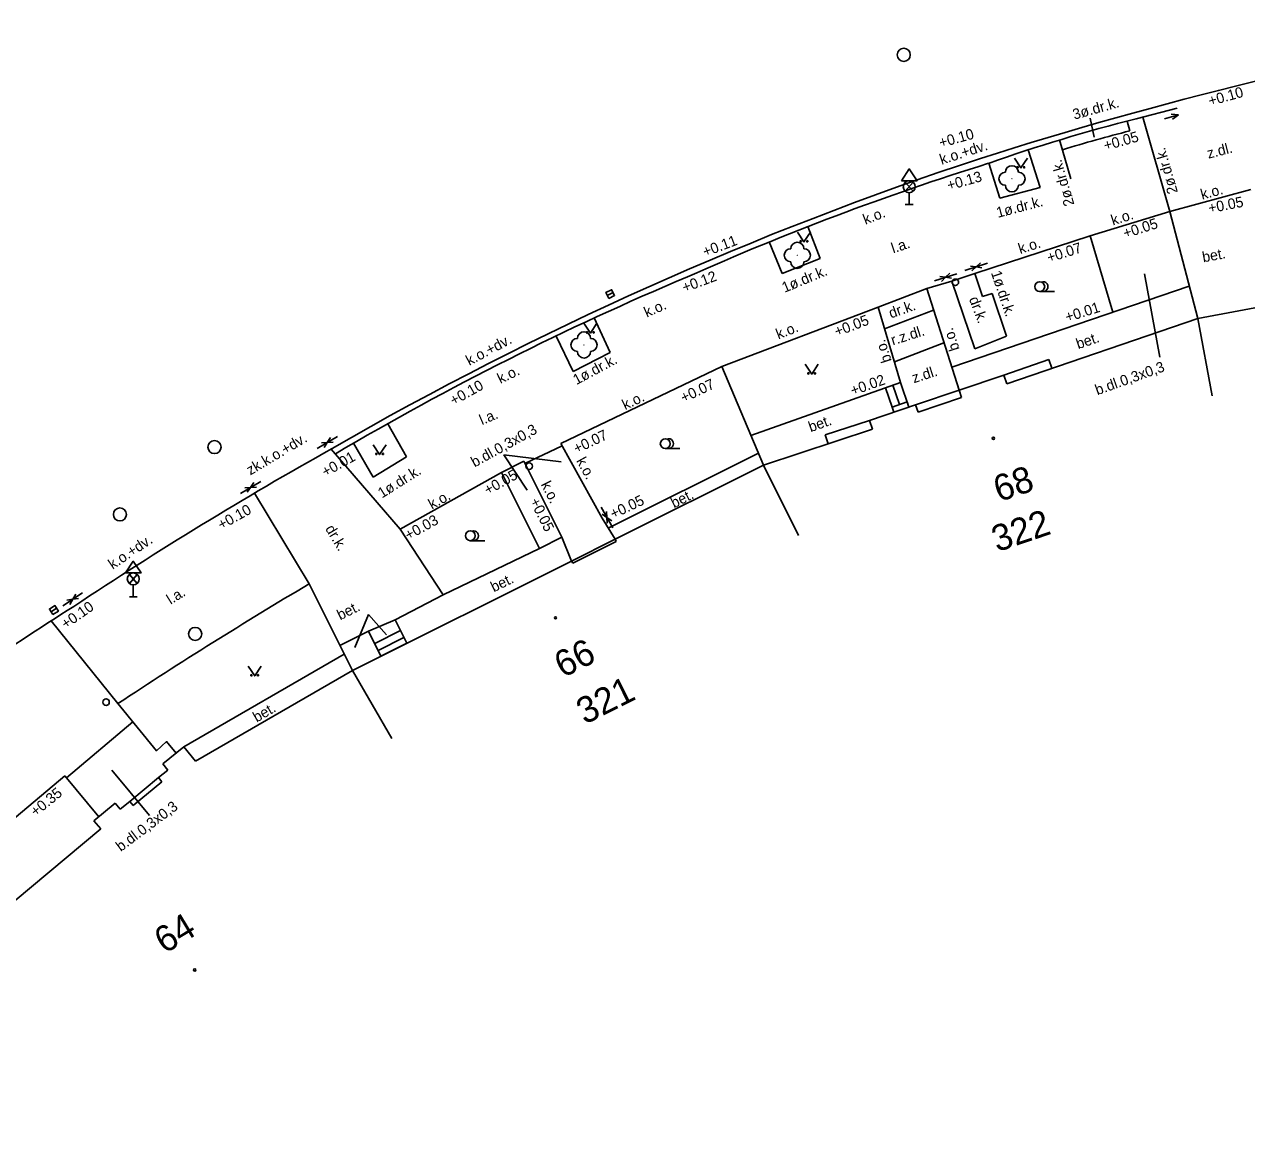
# Model space of a CAD drawing. Extents: x -597862 to -597276, y -1159156 to -1158889.
# Drawn here: x -597817.21 to -597770.58, y -1159122.27 to -1159079.98 of the extents above; entities that cross this region are included whole.
import ezdxf

# ---------------------------------------------------------------- set-up
doc = ezdxf.new("R2010")
doc.units = 0
for name, color, linetype in [('Vrstva 12', 7, 'Continuous'), ('Vrstva 14', 7, 'Continuous'), ('Vrstva 15', 7, 'Continuous'), ('Vrstva 24', 7, 'Continuous'), ('Vrstva 25', 7, 'Continuous'), ('Vrstva 26', 7, 'Continuous'), ('Vrstva 29', 7, 'Continuous'), ('Vrstva 4', 7, 'Continuous'), ('Vrstva 43', 7, 'Continuous'), ('Vrstva 44', 7, 'Continuous'), ('Vrstva 49', 7, 'Continuous'), ('Vrstva 5', 7, 'Continuous'), ('Vrstva 50', 7, 'Continuous'), ('Vrstva 7', 7, 'Continuous')]:
    doc.layers.add(name, color=color, linetype=linetype)

msp = doc.modelspace()

# ---------------------------------------------------------------- linework, layer by layer
at = {"layer": 'Vrstva 12'}
for points in [[(-597804.7, -1159104.63), (-597806.35, -1159101.33)], [(-597803.07, -1159102.7), (-597802.624, -1159103.594)], [(-597804.08, -1159103.14), (-597803.608, -1159104.085)], [(-597813.65, -1159105.9), (-597812.18, -1159107.7), (-597811.79, -1159107.35), (-597811.43, -1159107.793)]]:
    msp.add_lwpolyline(points, dxfattribs=at)
at = {"layer": 'Vrstva 14'}
for p, q in [((-597778.468, -1159090.175), (-597777.906, -1159090.175)), ((-597792.76, -1159096.167), (-597792.198, -1159096.167)), ((-597800.201, -1159099.681), (-597799.639, -1159099.681))]:
    msp.add_line(p, q, dxfattribs=at)
for points in [[(-597779.438, -1159085.081), (-597779.188, -1159085.456), (-597778.938, -1159085.081)], [(-597787.716, -1159087.906), (-597787.466, -1159088.281), (-597787.216, -1159087.906)], [(-597795.867, -1159091.383), (-597795.617, -1159091.758), (-597795.367, -1159091.383)], [(-597787.422, -1159092.948), (-597787.172, -1159093.323), (-597786.922, -1159092.948)], [(-597803.91, -1159096.02), (-597803.66, -1159096.395), (-597803.41, -1159096.02)], [(-597808.677, -1159104.469), (-597808.427, -1159104.844), (-597808.177, -1159104.469)]]:
    msp.add_lwpolyline(points, dxfattribs=at)
for centre, radius in [((-597779.313, -1159085.431), 0.025), ((-597779.063, -1159085.431), 0.025), ((-597779.53, -1159085.87), 0.00025), ((-597787.591, -1159088.256), 0.025), ((-597787.341, -1159088.256), 0.025), ((-597787.72, -1159088.79), 0.00025), ((-597778.468, -1159089.987), 0.188), ((-597795.742, -1159091.733), 0.025), ((-597795.492, -1159091.733), 0.025), ((-597795.86, -1159092.21), 0.00025), ((-597787.297, -1159093.298), 0.025), ((-597787.047, -1159093.298), 0.025), ((-597792.76, -1159095.979), 0.188), ((-597803.785, -1159096.37), 0.025), ((-597803.535, -1159096.37), 0.025), ((-597800.201, -1159099.493), 0.188), ((-597808.552, -1159104.819), 0.025), ((-597808.302, -1159104.819), 0.025)]:
    msp.add_circle(centre, radius, dxfattribs=at)
for centre, radius, start, end in [((-597779.78, -1159085.87), 0.25, 90, 270), ((-597779.53, -1159085.62), 0.25, 0, 180), ((-597779.28, -1159085.87), 0.25, 270, 90), ((-597779.53, -1159086.12), 0.25, 180, 360), ((-597787.97, -1159088.79), 0.25, 90, 270), ((-597787.72, -1159088.54), 0.25, 0, 180), ((-597787.47, -1159088.79), 0.25, 270, 90), ((-597787.72, -1159089.04), 0.25, 180, 360), ((-597778.343, -1159089.987), 0.188, 249.4944, 109.0474), ((-597795.86, -1159091.96), 0.25, 0, 180), ((-597796.11, -1159092.21), 0.25, 90, 270), ((-597795.61, -1159092.21), 0.25, 270, 90), ((-597795.86, -1159092.46), 0.25, 180, 360), ((-597792.635, -1159095.979), 0.188, 249.4944, 109.0474), ((-597800.076, -1159099.493), 0.188, 249.4944, 109.0474)]:
    msp.add_arc(centre, radius, start, end, dxfattribs=at)
at = {"layer": 'Vrstva 15'}
for p, q in [((-597784.1, -1159094.58), (-597784.36, -1159093.846)), ((-597783.815, -1159094.483), (-597784.077, -1159093.745))]:
    msp.add_line(p, q, dxfattribs=at)
for centre in [(-597780.235, -1159095.775), (-597796.948, -1159102.625), (-597810.713, -1159116.061)]:
    msp.add_circle(centre, 0.0438, dxfattribs=at)
at = {"layer": 'Vrstva 24'}
for centre in [(-597781.69, -1159089.82), (-597797.95, -1159096.84)]:
    msp.add_circle(centre, 0.125, dxfattribs=at)
at = {"layer": 'Vrstva 25'}
for p, q in [((-597794.971, -1159090.327), (-597794.749, -1159090.213)), ((-597816.195, -1159102.398), (-597815.985, -1159102.262))]:
    msp.add_line(p, q, dxfattribs=at)
for points in [[(-597794.914, -1159090.438), (-597794.692, -1159090.324), (-597794.806, -1159090.102), (-597795.028, -1159090.216)], [(-597816.127, -1159102.503), (-597815.917, -1159102.367), (-597816.053, -1159102.157), (-597816.263, -1159102.293)]]:
    msp.add_lwpolyline(points, close=True, dxfattribs=at)
for centre in [(-597783.66, -1159081.14), (-597809.96, -1159096.11), (-597813.57, -1159098.68), (-597810.7, -1159103.24)]:
    msp.add_circle(centre, 0.25, dxfattribs=at)
at = {"layer": 'Vrstva 26'}
msp.add_circle((-597814.1, -1159105.84), 0.125, dxfattribs=at)
at = {"layer": 'Vrstva 29'}
msp.add_lwpolyline([(-597784.033, -1159094.777), (-597783.461, -1159094.583), (-597783.528, -1159094.386), (-597784.1, -1159094.58)], close=True, dxfattribs=at)
at = {"layer": 'Vrstva 4'}
for p, q in [((-597772.44, -1159091.2), (-597763.253, -1159089.499)), ((-597779.728, -1159093.692), (-597772.44, -1159091.2)), ((-597771.894, -1159094.15), (-597772.44, -1159091.2)), ((-597779.84, -1159093.36), (-597778.12, -1159092.77)), ((-597778.12, -1159092.77), (-597778.006, -1159093.103)), ((-597781.548, -1159093.937), (-597779.84, -1159093.36)), ((-597779.728, -1159093.692), (-597779.84, -1159093.36)), ((-597783.207, -1159094.497), (-597781.548, -1159093.937)), ((-597781.548, -1159093.937), (-597781.451, -1159094.221)), ((-597784.96, -1159095.09), (-597783.207, -1159094.497)), ((-597783.207, -1159094.498), (-597783.11, -1159094.782)), ((-597784.96, -1159095.09), (-597786.66, -1159095.64)), ((-597784.848, -1159095.422), (-597784.96, -1159095.09)), ((-597789.01, -1159096.8), (-597784.848, -1159095.422)), ((-597786.66, -1159095.64), (-597786.546, -1159095.984)), ((-597794.672, -1159099.625), (-597789.01, -1159096.8)), ((-597787.671, -1159099.484), (-597789.01, -1159096.8)), ((-597796.337, -1159100.457), (-597794.672, -1159099.625)), ((-597794.672, -1159099.625), (-597794.627, -1159099.714)), ((-597804.7, -1159104.63), (-597796.337, -1159100.457)), ((-597796.337, -1159100.456), (-597796.292, -1159100.545)), ((-597810.689, -1159108.093), (-597804.7, -1159104.63)), ((-597803.198, -1159107.227), (-597804.7, -1159104.63)), ((-597811.93, -1159108.2), (-597811.13, -1159107.55)), ((-597811.13, -1159107.55), (-597810.689, -1159108.093)), ((-597811.741, -1159108.433), (-597812.095, -1159108.724)), ((-597811.741, -1159108.433), (-597811.93, -1159108.2)), ((-597813.198, -1159109.633), (-597812.095, -1159108.724)), ((-597811.967, -1159108.878), (-597813.07, -1159109.787)), ((-597812.095, -1159108.724), (-597811.967, -1159108.878)), ((-597813.75, -1159109.7), (-597814.56, -1159110.37)), ((-597813.556, -1159109.929), (-597813.75, -1159109.7)), ((-597813.198, -1159109.633), (-597813.556, -1159109.929)), ((-597813.07, -1159109.787), (-597813.198, -1159109.633)), ((-597814.56, -1159110.37), (-597814.298, -1159110.684)), ((-597814.298, -1159110.684), (-597828.192, -1159122.269))]:
    msp.add_line(p, q, dxfattribs=at)
for points in [[(-597802.864, -1159103.112), (-597803.848, -1159103.604)], [(-597802.731, -1159103.38), (-597803.714, -1159103.872)]]:
    msp.add_lwpolyline(points, dxfattribs=at)
at = {"layer": 'Vrstva 44'}
for p, q in [((-597783.3, -1159086), (-597783.6, -1159086.344)), ((-597783.6, -1159086), (-597783.3, -1159086.344)), ((-597783.45, -1159086.85), (-597783.45, -1159086.4)), ((-597783.6, -1159086.85), (-597783.3, -1159086.85)), ((-597812.91, -1159100.97), (-597813.21, -1159101.314)), ((-597813.21, -1159100.97), (-597812.91, -1159101.314)), ((-597813.06, -1159101.82), (-597813.06, -1159101.37)), ((-597813.21, -1159101.82), (-597812.91, -1159101.82))]:
    msp.add_line(p, q, dxfattribs=at)
for points in [[(-597783.75, -1159085.944), (-597783.15, -1159085.944), (-597783.45, -1159085.494), (-597783.75, -1159085.944)], [(-597813.36, -1159100.914), (-597812.76, -1159100.914), (-597813.06, -1159100.464), (-597813.36, -1159100.914)]]:
    msp.add_lwpolyline(points, dxfattribs=at)
for centre in [(-597783.45, -1159086.172), (-597813.06, -1159101.142)]:
    msp.add_circle(centre, 0.228, dxfattribs=at)
at = {"layer": 'Vrstva 49'}
for p, q in [((-597773.712, -1159083.578), (-597773.169, -1159083.428)), ((-597773.169, -1159083.428), (-597773.451, -1159083.408)), ((-597773.169, -1159083.428), (-597773.398, -1159083.592)), ((-597776.539, -1159083.557), (-597776.391, -1159084.288)), ((-597781.632, -1159089.492), (-597782.49, -1159089.768)), ((-597782.061, -1159089.63), (-597781.902, -1159089.474)), ((-597780.466, -1159089.095), (-597781.324, -1159089.371)), ((-597780.895, -1159089.233), (-597781.116, -1159089.201)), ((-597780.895, -1159089.233), (-597781.056, -1159089.389)), ((-597780.895, -1159089.233), (-597780.736, -1159089.077)), ((-597780.895, -1159089.233), (-597780.676, -1159089.268)), ((-597773.887, -1159092.674), (-597774.477, -1159089.493)), ((-597782.061, -1159089.63), (-597782.282, -1159089.598)), ((-597782.061, -1159089.63), (-597782.222, -1159089.786)), ((-597782.061, -1159089.63), (-597781.842, -1159089.665)), ((-597805.268, -1159095.71), (-597806.048, -1159096.162)), ((-597805.658, -1159095.936), (-597805.881, -1159095.952)), ((-597805.658, -1159095.936), (-597805.782, -1159096.123)), ((-597805.658, -1159095.936), (-597805.536, -1159095.749)), ((-597805.658, -1159095.936), (-597805.437, -1159095.923)), ((-597798.918, -1159096.405), (-597798.034, -1159097.75)), ((-597798.918, -1159096.405), (-597796.729, -1159096.671)), ((-597808.195, -1159097.423), (-597808.975, -1159097.875)), ((-597808.585, -1159097.649), (-597808.808, -1159097.665)), ((-597808.585, -1159097.649), (-597808.709, -1159097.836)), ((-597808.585, -1159097.649), (-597808.463, -1159097.462)), ((-597808.585, -1159097.649), (-597808.364, -1159097.636)), ((-597794.765, -1159099.188), (-597795.203, -1159098.4)), ((-597794.984, -1159098.794), (-597795.169, -1159098.666)), ((-597794.984, -1159098.794), (-597794.996, -1159098.571)), ((-597794.984, -1159098.794), (-597794.975, -1159099.015)), ((-597794.984, -1159098.794), (-597794.8, -1159098.92)), ((-597814.992, -1159101.672), (-597815.746, -1159102.166)), ((-597815.369, -1159101.919), (-597815.59, -1159101.947)), ((-597815.369, -1159101.919), (-597815.483, -1159102.113)), ((-597815.369, -1159101.919), (-597815.257, -1159101.726)), ((-597815.369, -1159101.919), (-597815.149, -1159101.894)), ((-597804.084, -1159102.5), (-597804.61, -1159103.759)), ((-597804.084, -1159102.5), (-597803.393, -1159103.269)), ((-597813.874, -1159108.445), (-597812.436, -1159110.166))]:
    msp.add_line(p, q, dxfattribs=at)
at = {"layer": 'Vrstva 5'}
for p, q in [((-597783.11, -1159094.782), (-597781.451, -1159094.221)), ((-597796.292, -1159100.545), (-597794.627, -1159099.714)), ((-597802.624, -1159103.594), (-597803.608, -1159104.085)), ((-597813.07, -1159109.787), (-597811.967, -1159108.878))]:
    msp.add_line(p, q, dxfattribs=at)
at = {"layer": 'Vrstva 7'}
for p, q in [((-597774.79, -1159083.58), (-597773.23, -1159083.18)), ((-597775.03, -1159084.04), (-597775.127, -1159083.666)), ((-597774.537, -1159083.515), (-597773.51, -1159087.12)), ((-597778.45, -1159086.2), (-597778.915, -1159084.768)), ((-597777.71, -1159084.39), (-597777.28, -1159085.87)), ((-597779.99, -1159086.61), (-597780.407, -1159085.272)), ((-597779.99, -1159086.61), (-597778.45, -1159086.2)), ((-597773.51, -1159087.12), (-597770.42, -1159086.28)), ((-597776.55, -1159088.05), (-597773.51, -1159087.12)), ((-597786.85, -1159088.91), (-597787.324, -1159087.696)), ((-597780.95, -1159089.48), (-597776.55, -1159088.05)), ((-597776.55, -1159088.05), (-597775.68, -1159090.96)), ((-597788.3, -1159089.48), (-597788.789, -1159088.28)), ((-597788.3, -1159089.48), (-597786.85, -1159088.91)), ((-597781.82, -1159089.78), (-597780.95, -1159089.48)), ((-597780.95, -1159089.48), (-597780.65, -1159090.36)), ((-597782.78, -1159090.06), (-597781.82, -1159089.78)), ((-597781.826, -1159093.062), (-597772.764, -1159089.963)), ((-597780.94, -1159092.36), (-597781.82, -1159089.78)), ((-597784.64, -1159090.77), (-597782.78, -1159090.06)), ((-597781.548, -1159093.937), (-597782.78, -1159090.06)), ((-597780.65, -1159090.36), (-597780.29, -1159090.25)), ((-597780.29, -1159090.25), (-597779.74, -1159091.87)), ((-597790.6, -1159093.04), (-597784.64, -1159090.77)), ((-597784.64, -1159090.77), (-597783.78, -1159093.64)), ((-597784.391, -1159091.601), (-597782.518, -1159090.886)), ((-597794.86, -1159092.5), (-597795.47, -1159091.182)), ((-597796.28, -1159093.22), (-597796.929, -1159091.87)), ((-597784.017, -1159092.85), (-597782.123, -1159092.127)), ((-597779.74, -1159091.87), (-597780.94, -1159092.36)), ((-597796.28, -1159093.22), (-597794.86, -1159092.5)), ((-597796.74, -1159095.97), (-597790.6, -1159093.04)), ((-597783.78, -1159093.64), (-597789.489, -1159095.666)), ((-597783.78, -1159093.64), (-597783.461, -1159094.583)), ((-597802.64, -1159096.48), (-597803.351, -1159095.217)), ((-597804.653, -1159095.962), (-597803.91, -1159097.26)), ((-597795.17, -1159098.82), (-597796.74, -1159095.97)), ((-597805.511, -1159096.183), (-597802.88, -1159099.24)), ((-597803.91, -1159097.26), (-597802.64, -1159096.48)), ((-597798.115, -1159096.739), (-597796.692, -1159096.058)), ((-597794.936, -1159099.198), (-597789.205, -1159096.338)), ((-597799.008, -1159097.074), (-597798.16, -1159096.65)), ((-597796.71, -1159099.55), (-597798.16, -1159096.65)), ((-597802.88, -1159099.24), (-597799.008, -1159097.074)), ((-597797.558, -1159099.974), (-597799.008, -1159097.074)), ((-597808.44, -1159097.87), (-597806.35, -1159101.33)), ((-597794.672, -1159099.625), (-597795.17, -1159098.82)), ((-597801.24, -1159101.75), (-597802.88, -1159099.24)), ((-597796.71, -1159099.55), (-597797.558, -1159099.974)), ((-597796.71, -1159099.55), (-597796.337, -1159100.457)), ((-597797.558, -1159099.974), (-597801.24, -1159101.75)), ((-597803.07, -1159102.7), (-597801.24, -1159101.75)), ((-597816.193, -1159102.735), (-597813.65, -1159105.9)), ((-597804.08, -1159103.14), (-597803.07, -1159102.7)), ((-597804.08, -1159103.14), (-597805.172, -1159103.686)), ((-597811.13, -1159107.55), (-597805.01, -1159104.011)), ((-597815.606, -1159108.737), (-597813.081, -1159106.597)), ((-597815.67, -1159108.66), (-597823.47, -1159115.15)), ((-597814.375, -1159110.217), (-597815.67, -1159108.66))]:
    msp.add_line(p, q, dxfattribs=at)
for points in [[(-597773.51, -1159087.12), (-597772.44, -1159091.2)], [(-597790.6, -1159093.04), (-597789.01, -1159096.8)]]:
    msp.add_lwpolyline(points, dxfattribs=at)
for centre, radius, start, end in [((-597733.048, -1159235.075), 157.382, 99.77922, 107.63596), ((-597758.996, -1159146.186), 64.567, 104.15924, 109.38831), ((-597758.996, -1159146.186), 64.181, 104.46744, 106.85239), ((-597739.238, -1159210.999), 132.569, 108.23901, 119.97359), ((-597749.151, -1159185.592), 105.075, 107.31828, 114.01243), ((-597748.742, -1159192.175), 111.279, 112.82532, 120.5773), ((-597730.315, -1159230.127), 153.608, 119.29234, 123.60439), ((-597717.527, -1159251.328), 174.324, 120.6322, 123.46319), ((-597776.625, -1159164.411), 73.277, 121.88364, 125.54822)]:
    msp.add_arc(centre, radius, start, end, dxfattribs=at)

# ---------------------------------------------------------------- texts
at = {"layer": 'Vrstva 43'}
for s, rotation, p in [('68', 18.6732, (-597780.026, -1159098.214)), ('322', 18.6732, (-597780.096, -1159100.124)), ('66', 26.5212, (-597796.669, -1159104.932)), ('321', 26.5212, (-597795.826, -1159106.71)), ('64', 31.2099, (-597811.864, -1159115.466))]:
    msp.add_text(s, height=1, rotation=rotation, dxfattribs=at).set_placement(p)
at = {"layer": 'Vrstva 49'}
for s, rotation, p in [('3ø.dr.k.', 15.6579, (-597777.15, -1159083.617)), ('k.o.+dv.', 18.0093, (-597782.214, -1159085.337)), ('2ø.dr.k.', 106.2007, (-597773.193, -1159086.386)), ('z.dl.', 14.3268, (-597772.03, -1159085.106)), ('2ø.dr.k.', 106.2007, (-597777.144, -1159086.848)), ('k.o.', 15.208, (-597772.271, -1159086.67)), ('1ø.dr.k.', 14.5955, (-597780.066, -1159087.361)), ('k.o.', 21.219, (-597785.124, -1159087.625)), ('k.o.', 17.5993, (-597775.677, -1159087.655)), ('l.a.', 18.7815, (-597784.059, -1159088.72)), ('k.o.', 17.5993, (-597779.216, -1159088.742)), ('bet.', 10.493, (-597772.229, -1159089.06)), ('1ø.dr.k.', 22.479, (-597788.209, -1159090.223)), ('1ø.dr.k.', 288.7527, (-597780.336, -1159089.453)), ('dr.k.', 290.6841, (-597781.176, -1159090.453)), ('k.o.', 23.8391, (-597793.464, -1159091.17)), ('dr.k.', 19.2693, (-597784.147, -1159091.201)), ('k.o.', 21.6646, (-597788.442, -1159092.003)), ('r.z.dl.', 17.6288, (-597784.075, -1159092.231)), ('b.o.', 107.6288, (-597781.525, -1159092.372)), ('bet.', 18.8795, (-597777.002, -1159092.375)), ('k.o.+dv.', 28.0038, (-597800.237, -1159093.012)), ('b.o.', 107.6288, (-597784.116, -1159092.819)), ('1ø.dr.k.', 28.1035, (-597796.149, -1159093.745)), ('k.o.', 25.9505, (-597799.05, -1159093.701)), ('z.dl.', 17.6288, (-597783.273, -1159093.674)), ('b.dl.0,3x0,3', 19.6904, (-597776.272, -1159094.134)), ('k.o.', 25.5104, (-597794.289, -1159094.701)), ('l.a.', 23.2496, (-597799.753, -1159095.276)), ('bet.', 19.5387, (-597787.212, -1159095.544)), ('b.dl.0,3x0,3', 28.7548, (-597800.037, -1159096.889)), ('zk.k.o.+dv.', 30.7717, (-597808.594, -1159097.195)), ('k.o.', 298.8494, (-597796.168, -1159096.63)), ('1ø.dr.k.', 32.0587, (-597803.571, -1159098.074)), ('k.o.', 296.565, (-597797.513, -1159097.53)), ('bet.', 26.521, (-597792.425, -1159098.447)), ('k.o.', 28.7548, (-597801.665, -1159098.497)), ('dr.k.', 300.8037, (-597805.749, -1159099.222)), ('k.o.+dv.', 33.797, (-597813.847, -1159100.791)), ('bet.', 25.7502, (-597799.304, -1159101.653)), ('l.a.', 32.0477, (-597811.635, -1159102.131)), ('bet.', 26.2143, (-597805.166, -1159102.722)), ('bet.', 30.0394, (-597808.35, -1159106.625)), ('b.dl.0,3x0,3', 36.8397, (-597813.536, -1159111.564))]:
    msp.add_text(s, height=0.4, rotation=rotation, dxfattribs=at).set_placement(p)
at = {"layer": 'Vrstva 50'}
for s, rotation, p in [('+0.10', 15.675, (-597771.97, -1159083.098)), ('+0.10', 15.675, (-597782.25, -1159084.693)), ('+0.05', 15.675, (-597775.964, -1159084.8)), ('+0.13', 15.675, (-597781.945, -1159086.32)), ('+0.05', 10.9013, (-597771.998, -1159087.188)), ('+0.05', 17.5993, (-597775.214, -1159088.149)), ('+0.11', 20.7306, (-597791.242, -1159088.858)), ('+0.07', 17.5993, (-597778.121, -1159089.078)), ('+0.12', 20.7306, (-597792.024, -1159090.22)), ('+0.01', 17.5993, (-597777.426, -1159091.349)), ('+0.05', 20.8505, (-597786.213, -1159091.9)), ('+0.10', 29.2607, (-597800.838, -1159094.535)), ('+0.07', 25.5104, (-597792.059, -1159094.427)), ('+0.02', 19.5387, (-597785.606, -1159094.152)), ('+0.07', 25.5104, (-597796.146, -1159096.37)), ('+0.01', 29.2607, (-597805.728, -1159097.26)), ('+0.05', 29.2227, (-597799.535, -1159097.95)), ('+0.10', 29.2607, (-597809.696, -1159099.278)), ('+0.05', 296.565, (-597797.941, -1159098.168)), ('+0.05', 25.5104, (-597794.745, -1159098.86)), ('+0.03', 29.2227, (-597802.558, -1159099.673)), ('+0.10', 35.0872, (-597815.635, -1159103.068)), ('+0.35', 39.1358, (-597816.785, -1159110.23))]:
    msp.add_text(s, height=0.4, rotation=rotation, dxfattribs=at).set_placement(p)

doc.saveas('drawing.dxf')
